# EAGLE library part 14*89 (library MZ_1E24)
Quad line receivers BUFFER,
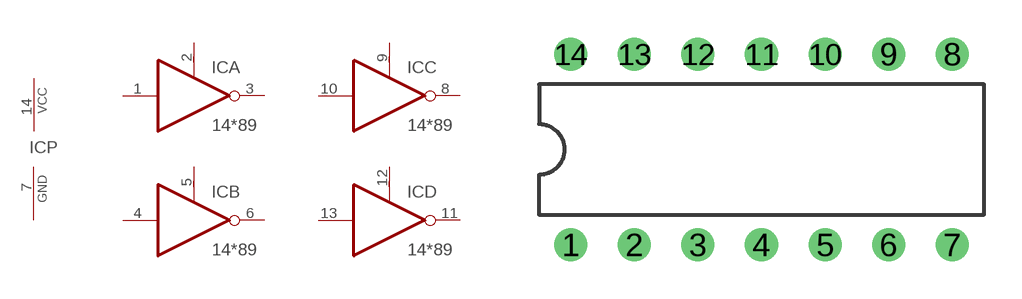
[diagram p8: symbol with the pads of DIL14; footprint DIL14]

Designator prefix IC; gates A=INTERFACE_1489 B=INTERFACE_1489 C=INTERFACE_1489 D=INTERFACE_1489 P=PWRN

## 1489  [DIL14]
1  A:I  in
2  A:RC  in
3  A:O  out
4  B:I  in
5  B:RC  in
6  B:O  out
7  P:GND  pwr
8  C:O  out
9  C:RC  in
10  C:I  in
11  D:O  out
12  D:RC  in
13  D:I  in
14  P:VCC  pwr

## Footprint DIL14 (pad centres in mm)
Dual In Line Package
drill 0.813 round: 1 -7.62,-3.81; 2 -5.08,-3.81; 3 -2.54,-3.81; 4 0,-3.81; 5 2.54,-3.81; 6 5.08,-3.81; 7 7.62,-3.81; 8 7.62,3.81; 9 5.08,3.81; 10 2.54,3.81; 11 0,3.81; 12 -2.54,3.81; 13 -5.08,3.81; 14 -7.62,3.81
